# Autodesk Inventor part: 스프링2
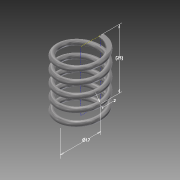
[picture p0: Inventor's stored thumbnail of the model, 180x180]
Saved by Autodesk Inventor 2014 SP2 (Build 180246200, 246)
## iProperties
Created: 2016-03
Part Number: 스프링2
Material: 스테인레스 스틸
Document SubType Name: Modeling
Designer: apexhp001
Density: 8.08 g/cm^3
Appearance: 반연마
Mass: 6.6143 g
Surface Area: 16.6857 cm^2
Volume: 0.818602 cm^3
Author: apexhp001
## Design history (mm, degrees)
sketch "스케치1"
  geometry: L1 (0, 0)-(8.5, 0); L2 (8.5, 0)-(8.5, 17.5); L3 (8.5, 17.5)-(0, 17.5); L4 (0, 17.5)-(0, 0); C1 r 1 at (8.5, 0)
  constraints: 8 end point, 2 parallel, 1 centre point, 1 coincident, 1 horizontal, 1 perpendicular
  dimensions: "d0" = 17.5 distance of L1.end L2.end (derived); "d1" = 17 diameter of L1.end L4; "d2" = 2 diameter of C1
feature "코일1" sketch "스케치1" pitch "d3" = 10; turns "d5" = 5; dims "d4" = 17.5 (= d0), "d6" = 0, angle "d7" = 90 deg, angle "d8" = 90 deg, "d9" = 0, "d10" = 0
sketch "스케치2"
  geometry: L1 (0, 9.5)-(0, 7.5) reference; 1 further point
  constraints: 1 vertical alignment
extrude "돌출1" cut sketch "스케치2" distance "d11" = 10; taper "d12" = 0 deg
node "작업 평면1"
sketch "스케치3"
  geometry: L1 (0, 7.5)-(0, 9.5) reference; 1 further point
  constraints: 1 vertical alignment
extrude "돌출2" cut sketch "스케치3" distance "d14" = 10; taper "d15" = 0 deg
node "솔리드1"
node "절단 모서리 투영1"
node "절단 모서리 투영2"
other parameters: "d13" = 17.5 (= d0)
